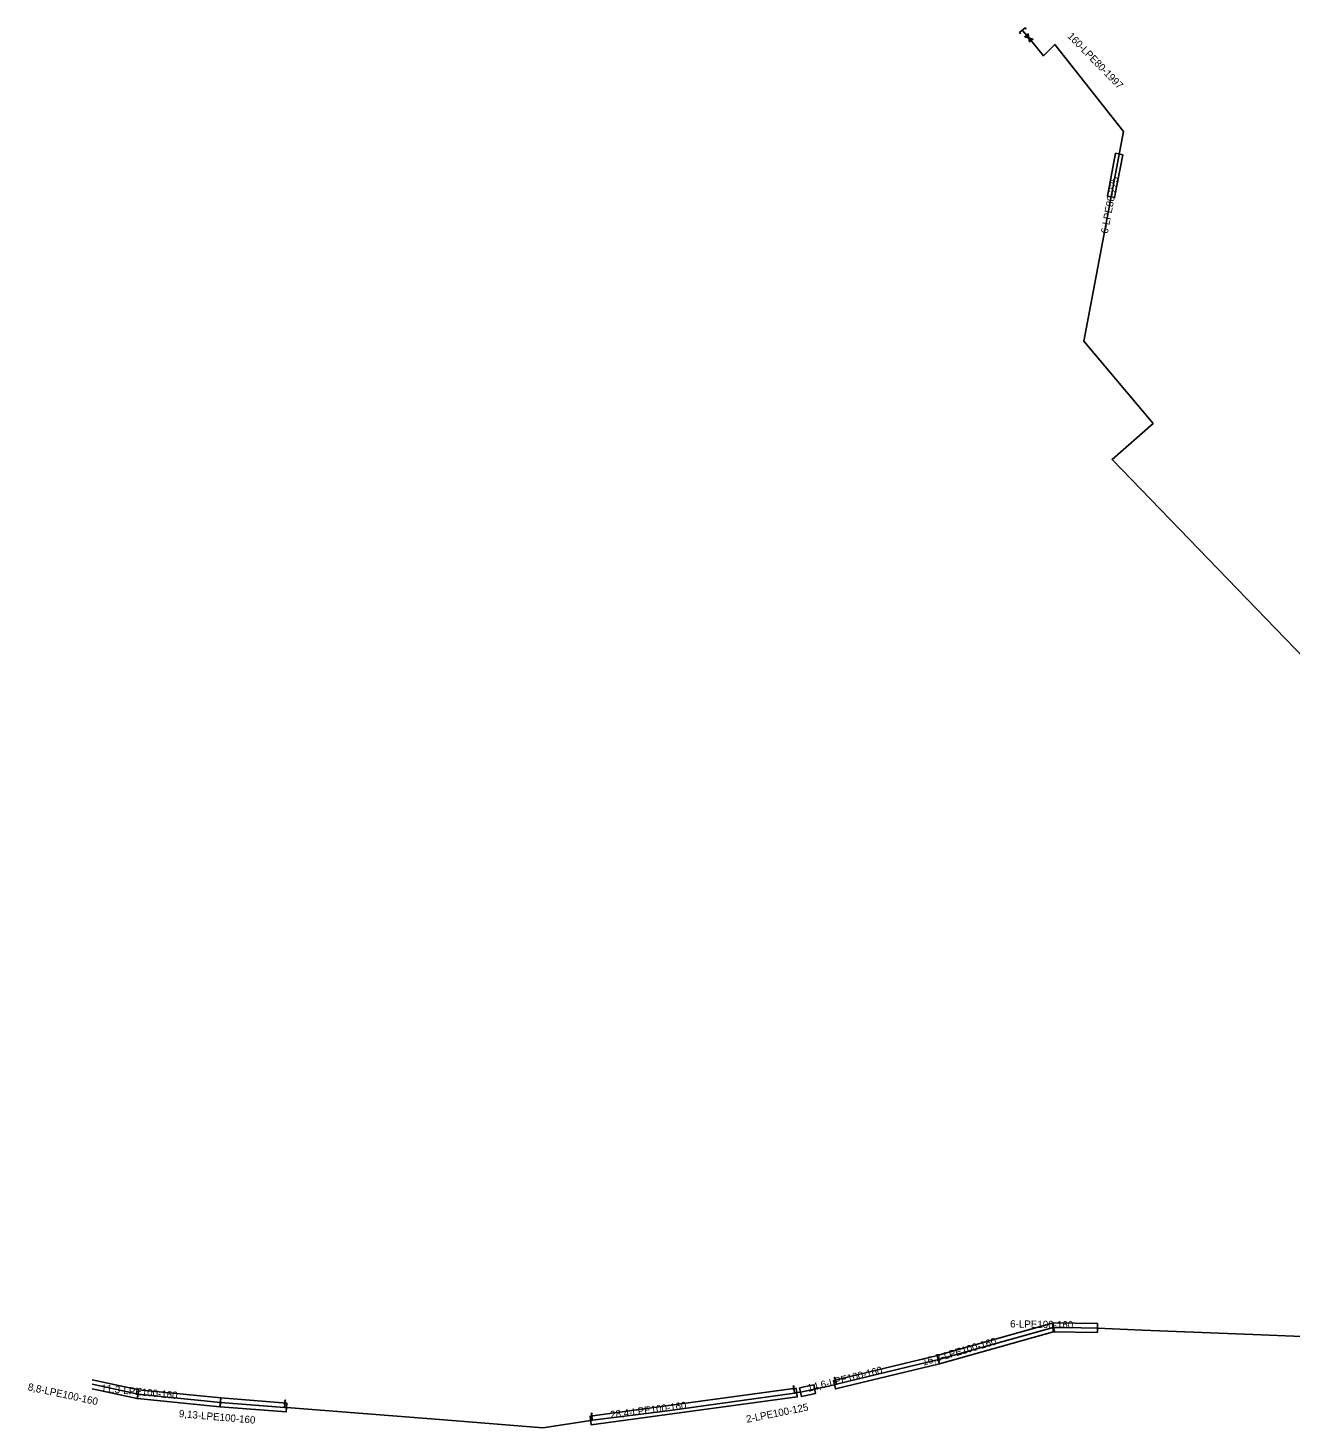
# Model space of a CAD drawing. Extents: x -762509 to -761250, y -1153000 to -1152256.
# Drawn here: x -762508.8 to -762336.3, y -1152949.2 to -1152758 of the extents above; entities that cross this region are included whole.
import ezdxf

# ---------------------------------------------------------------- set-up
doc = ezdxf.new("R2010")
doc.units = 0
for name, color, linetype in [('Vrstva 21', 7, 'Continuous'), ('Vrstva 22', 7, 'Continuous'), ('Vrstva 23', 7, 'Continuous'), ('Vrstva 28', 7, 'Continuous'), ('Vrstva 29', 7, 'Continuous')]:
    doc.layers.add(name, color=color, linetype=linetype)

msp = doc.modelspace()

# ---------------------------------------------------------------- linework, layer by layer
at = {"layer": 'Vrstva 21'}
for points in [[(-762371.98, -1152759.36), (-762372.88, -1152758.27)], [(-762229.19, -1152811.83), (-762234.58, -1152808.18), (-762266.76, -1152814.86), (-762319.87, -1152859.08), (-762360.62, -1152816.89), (-762355.03, -1152811.99), (-762364.5, -1152800.75), (-762359.08, -1152772.07), (-762368.47, -1152760.2), (-762370.01, -1152761.74), (-762371.98, -1152759.36)], [(-762500, -1152943.26), (-762493.74, -1152944.63), (-762482.48, -1152945.74), (-762473.7, -1152946.43), (-762473.44, -1152946.45), (-762451.97, -1152948.11), (-762438.42, -1152949.24), (-762431.88, -1152948.22), (-762431.65, -1152948.19), (-762421.37, -1152946.89), (-762404.02, -1152944.46), (-762403.74, -1152944.41), (-762403.21, -1152944.35), (-762401.29, -1152943.95), (-762398.57, -1152943.33), (-762398.3, -1152943.27), (-762384.37, -1152939.9), (-762368.67, -1152935.49), (-762367.09, -1152935.51)], [(-762367.09, -1152935.51), (-762362.63, -1152935.58), (-762356.49, -1152935.86), (-762341.39, -1152936.46), (-762323.51, -1152937.19), (-762322.03, -1152937.21), (-762321.41, -1152937.33), (-762319.93, -1152937.48), (-762309.7, -1152937.99), (-762305.82, -1152938.43), (-762303.5, -1152938.57)]]:
    msp.add_lwpolyline(points, dxfattribs=at)
at = {"layer": 'Vrstva 22'}
msp.add_lwpolyline([(-762371.896, -1152759.893), (-762372.104, -1152758.746), (-762372.555, -1152759.141), (-762371.445, -1152759.498), (-762371.896, -1152759.893)], dxfattribs=at)
at = {"layer": 'Vrstva 23'}
msp.add_lwpolyline([(-762372.367, -1152758.106), (-762372.494, -1152757.951), (-762373.265, -1152758.588), (-762373.138, -1152758.742)], dxfattribs=at)
at = {"layer": 'Vrstva 28'}
for p, q in [((-762398.442, -1152942.718), (-762398.55, -1152942.302)), ((-762404.115, -1152943.898), (-762404.186, -1152943.474)), ((-762404.092, -1152944.036), (-762404.02, -1152944.46)), ((-762398.407, -1152942.854), (-762398.3, -1152943.27)), ((-762473.666, -1152946.001), (-762473.7, -1152946.43)), ((-762473.655, -1152945.862), (-762473.621, -1152945.433)), ((-762431.727, -1152947.625), (-762431.785, -1152947.199)), ((-762431.708, -1152947.764), (-762431.65, -1152948.19))]:
    msp.add_line(p, q, dxfattribs=at)
for points in [[(-762398.575, -1152942.484), (-762398.55, -1152942.302), (-762398.439, -1152942.449)], [(-762404.227, -1152943.653), (-762404.186, -1152943.474), (-762404.089, -1152943.63)], [(-762473.704, -1152945.597), (-762473.621, -1152945.433), (-762473.564, -1152945.608)], [(-762431.832, -1152947.377), (-762431.785, -1152947.199), (-762431.693, -1152947.358)]]:
    msp.add_lwpolyline(points, dxfattribs=at)
for centre in [(-762398.425, -1152942.786), (-762404.103, -1152943.967), (-762473.661, -1152945.932), (-762431.718, -1152947.695)]:
    msp.add_circle(centre, 0.07, dxfattribs=at)
at = {"layer": 'Vrstva 29'}
for points in [[(-762359.17, -1152775.26), (-762360.15, -1152775.07), (-762361.27, -1152780.95), (-762360.28, -1152781.13)], [(-762368.83, -1152934.91), (-762384.53, -1152939.32), (-762384.21, -1152940.48), (-762368.51, -1152936.07)], [(-762362.62, -1152934.98), (-762368.66, -1152934.89), (-762368.68, -1152936.09), (-762362.64, -1152936.18)], [(-762384.51, -1152939.32), (-762398.71, -1152942.75), (-762398.43, -1152943.91), (-762384.23, -1152940.48)], [(-762493.8, -1152945.23), (-762482.54, -1152946.34), (-762482.42, -1152945.14), (-762493.68, -1152944.03)], [(-762403.82, -1152943.82), (-762431.96, -1152947.63), (-762431.8, -1152948.81), (-762403.66, -1152945)], [(-762401.41, -1152943.36), (-762403.33, -1152943.76), (-762403.09, -1152944.94), (-762401.17, -1152944.54)], [(-762482.53, -1152946.34), (-762473.49, -1152947.05), (-762473.39, -1152945.85), (-762482.43, -1152945.14)]]:
    msp.add_lwpolyline(points, close=True, dxfattribs=at)
msp.add_lwpolyline([(-762500, -1152943.89), (-762493.87, -1152945.22), (-762493.61, -1152944.04), (-762500, -1152942.66)], dxfattribs=at)

# ---------------------------------------------------------------- texts
at = {"layer": 'Vrstva 21'}
msp.add_text('160-LPE80-1997', height=1, rotation=314.40934, dxfattribs=at).set_placement((-762366.8, -1152759.15))
at = {"layer": 'Vrstva 29'}
for s, rotation, p in [('6-LPE80-225', 79.28275, (-762361.22, -1152786.1)), ('6-LPE100-160', 359.01529, (-762374.57, -1152935.5)), ('16,3-LPE100-160', 16.18022, (-762386.41, -1152940.73)), ('14,6-LPE100-160', 13.92989, (-762402.12, -1152944.3)), ('8,8-LPE100-160', 347.77382, (-762508.86, -1152944.07)), ('11,3-LPE100-160', 354.37003, (-762498.82, -1152944.26)), ('28,4-LPE100-160', 7.26523, (-762429.15, -1152947.94)), ('2-LPE100-125', 11.33171, (-762410.52, -1152948.53)), ('9,13-LPE100-160', 355.01883, (-762488.19, -1152947.75))]:
    msp.add_text(s, height=1, rotation=rotation, dxfattribs=at).set_placement(p)

doc.saveas('drawing.dxf')
